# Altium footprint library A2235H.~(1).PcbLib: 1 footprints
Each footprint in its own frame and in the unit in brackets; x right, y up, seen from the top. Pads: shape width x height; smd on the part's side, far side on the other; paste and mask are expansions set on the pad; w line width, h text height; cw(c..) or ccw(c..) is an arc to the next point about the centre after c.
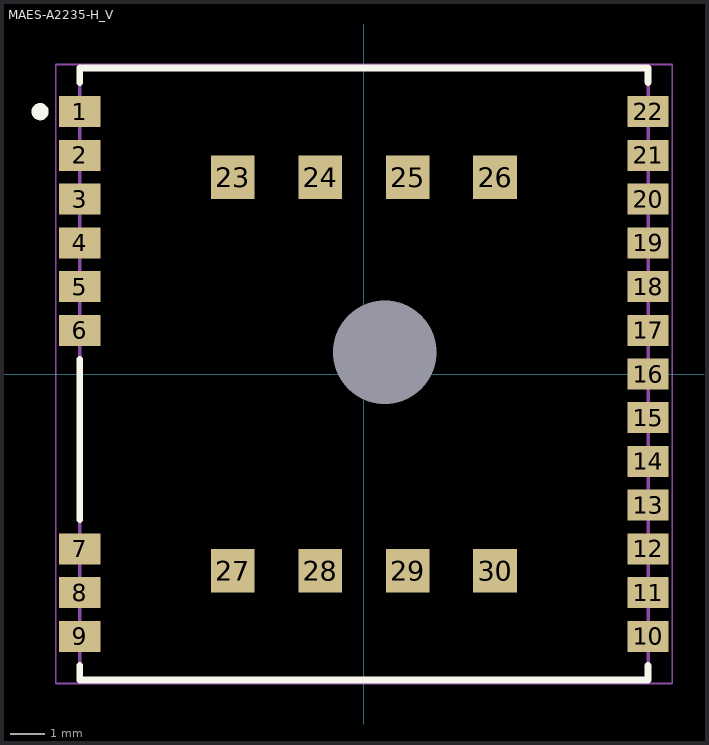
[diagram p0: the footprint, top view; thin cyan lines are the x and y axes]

## MAES-A2235-H_V [mm] "SMD, 30-Leads, Body 17.78x16.51mm"
height 7.11
pads (31):
  rect 1.2x0.9 smd: 1(-8.255,7.62) 2(-8.255,6.35) 3(-8.255,5.08) 4(-8.255,3.81) 5(-8.255,2.54) 6(-8.255,1.27) 7(-8.255,-5.08) 8(-8.255,-6.35) 9(-8.255,-7.62) 10(8.255,-7.62) 11(8.255,-6.35) 12(8.255,-5.08) 13(8.255,-3.81) 14(8.255,-2.54) 15(8.255,-1.27) 16(8.255,0) 17(8.255,1.27) 18(8.255,2.54) 19(8.255,3.81) 20(8.255,5.08) 21(8.255,6.35) 22(8.255,7.62)
  rect 1.27x1.27 smd: 23(-3.81,5.715) 24(-1.27,5.715) 25(1.27,5.715) 26(3.81,5.715) 27(-3.81,-5.715) 28(-1.27,-5.715) 29(1.27,-5.715) 30(3.81,-5.715)
  round 2.7 hole 3 unplated: ""(0.605,0.63)
Top Overlay:
  lines w0.2: -8.255,-8.47 -8.255,-8.89 8.255,-8.89 8.255,-8.47 ; -8.255,-4.23 -8.255,0.42 ; -8.255,8.47 -8.255,8.89 8.255,8.89 8.255,8.47
  lines w0.25: -9.405,7.495 cw(c-9.405,7.62) -9.349,7.508
Mechanical 13:
  lines w0.1: -8.255,-8.89 8.255,-8.89 8.255,8.89 -8.255,8.89 -8.255,-8.89
Mechanical 15:
  lines w0.05: -8.955,-8.99 8.955,-8.99 8.955,8.99 -8.955,8.99 -8.955,-8.99
  lines w0.1: -0.5,0 0.5,0 ; 0,-0.5 0,0.5
3D body: height 7.11, standoff 0, extent -8.254,-8.889 8.254,8.889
